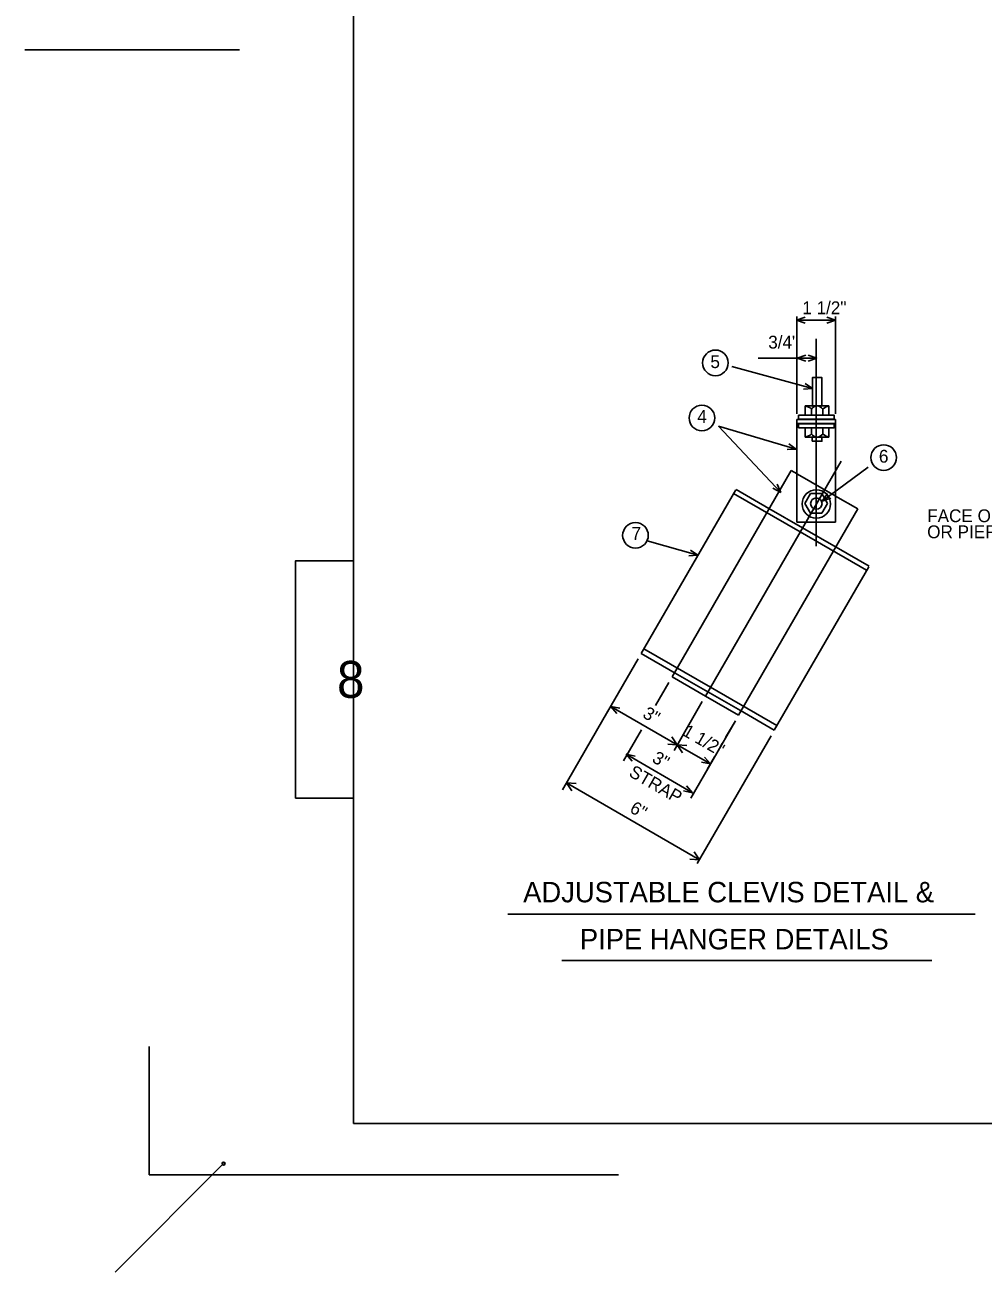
# Model space of a CAD drawing. Extents: x 15000 to 15012.1, y 999.8 to 1007.9.
# Drawn here: x 14999.988 to 15003.107, y 999.805 to 1003.866 of the extents above; entities that cross this region are included whole.
import ezdxf

# ---------------------------------------------------------------- set-up
doc = ezdxf.new("R2010")
doc.units = 0
for name, color, linetype in [('Level 1', 7, 'Continuous'), ('Level 2', 7, 'Continuous'), ('Level 37', 7, 'Continuous'), ('Level 49', 7, 'Continuous')]:
    doc.layers.add(name, color=color, linetype=linetype)

msp = doc.modelspace()

# ---------------------------------------------------------------- linework, layer by layer
at = {"layer": 'Level 1'}
for p, q in [((15001.0578, 1000.2885), (15001.0578, 1007.2814)), ((15000.3918, 1000.5391), (15000.3918, 1000.122)), ((15001.0578, 1000.2885), (15011.5058, 1000.2885)), ((15000.3918, 1000.122), (15001.9196, 1000.122))]:
    msp.add_line(p, q, dxfattribs=at)
msp.add_lwpolyline([(15001.0578, 1002.1216), (15000.8688, 1002.1216), (15000.8688, 1001.3486), (15001.0578, 1001.3486)], close=True, dxfattribs=at)
at = {"layer": 'Level 2'}
for p, q in [((15002.4992, 1002.9043), (15002.5273, 1002.914)), ((15002.4992, 1002.9043), (15002.6266, 1002.9043)), ((15002.5273, 1002.8945), (15002.4992, 1002.9043)), ((15002.5011, 1002.5994), (15002.5011, 1002.9172)), ((15002.5984, 1002.914), (15002.6266, 1002.9043)), ((15002.6266, 1002.9043), (15002.5984, 1002.8945)), ((15002.6261, 1002.5994), (15002.6261, 1002.9172)), ((15002.5636, 1002.8442), (15002.5636, 1002.1688)), ((15002.3744, 1002.7807), (15002.5654, 1002.7807)), ((15002.5015, 1002.7807), (15002.5297, 1002.7904)), ((15002.5297, 1002.7709), (15002.5015, 1002.7807)), ((15002.5373, 1002.7904), (15002.5654, 1002.7807)), ((15002.5654, 1002.7807), (15002.5373, 1002.7709)), ((15002.552, 1002.6819), (15002.289, 1002.7537)), ((15002.5274, 1002.6988), (15002.552, 1002.6819)), ((15002.552, 1002.6819), (15002.5223, 1002.6799)), ((15002.5482, 1002.5953), (15002.5482, 1002.6158)), ((15002.5848, 1002.5953), (15002.5848, 1002.6155)), ((15002.6261, 1002.5808), (15002.5011, 1002.5808)), ((15002.5011, 1002.2474), (15002.5011, 1002.5808)), ((15002.6261, 1002.5683), (15002.5011, 1002.5683)), ((15002.6261, 1002.2474), (15002.6261, 1002.5808)), ((15002.4487, 1002.3439), (15002.2453, 1002.5598)), ((15002.2453, 1002.5598), (15002.4988, 1002.4848)), ((15002.5482, 1002.5542), (15002.5482, 1002.5338)), ((15002.5848, 1002.5543), (15002.5848, 1002.534)), ((15002.4988, 1002.4848), (15002.469, 1002.4834)), ((15002.4745, 1002.5021), (15002.4988, 1002.4848)), ((15002.2028, 1001.6808), (15002.6446, 1002.446)), ((15002.0946, 1001.7433), (15002.4823, 1002.415)), ((15002.5013, 1002.4041), (15002.4823, 1002.415)), ((15002.5833, 1002.3158), (15002.7327, 1002.4263)), ((15002.4364, 1002.3711), (15002.4487, 1002.3439)), ((15002.6251, 1002.3326), (15002.5027, 1002.4033)), ((15001.9943, 1001.8195), (15002.3015, 1002.3518)), ((15002.5113, 1002.2152), (15002.2948, 1002.3402)), ((15002.4097, 1002.2918), (15002.3026, 1002.3537)), ((15002.4487, 1002.3439), (15002.4223, 1002.3578)), ((15002.5268, 1002.308), (15002.5454, 1002.34)), ((15002.5454, 1002.34), (15002.5823, 1002.34)), ((15002.5823, 1002.34), (15002.6008, 1002.308)), ((15002.5833, 1002.3158), (15002.6001, 1002.3403)), ((15002.6117, 1002.3247), (15002.5833, 1002.3158)), ((15002.6269, 1002.3315), (15002.6988, 1002.29)), ((15002.3111, 1001.6183), (15002.6988, 1002.29)), ((15002.5191, 1002.2287), (15002.4097, 1002.2918)), ((15002.5453, 1002.276), (15002.5268, 1002.308)), ((15002.5658, 1002.3081), (15002.5638, 1002.3081)), ((15002.6008, 1002.308), (15002.5823, 1002.276)), ((15002.6261, 1002.2474), (15002.5011, 1002.2474)), ((15002.5823, 1002.276), (15002.5453, 1002.276)), ((15002.5113, 1002.2152), (15002.7278, 1002.0902)), ((15002.5191, 1002.2287), (15002.6285, 1002.1655)), ((15002.1788, 1002.1391), (15002.013, 1002.1861)), ((15002.6285, 1002.1655), (15002.7356, 1002.1037)), ((15002.1788, 1002.1391), (15002.1491, 1002.1375)), ((15002.1543, 1002.1561), (15002.1788, 1002.1391)), ((15002.4272, 1001.5695), (15002.7345, 1002.1018)), ((15001.9838, 1001.8015), (15001.8843, 1001.629)), ((15002.1045, 1001.7558), (15001.9943, 1001.8195)), ((15002.2193, 1001.7094), (15002.0028, 1001.8344)), ((15002.2107, 1001.6945), (15002.1045, 1001.7558)), ((15002.0841, 1001.7253), (15002.0405, 1001.6497)), ((15002.2028, 1001.6808), (15002.0946, 1001.7433)), ((15002.2028, 1001.6808), (15002.3111, 1001.6183)), ((15002.2107, 1001.6945), (15002.317, 1001.6332)), ((15002.2193, 1001.7094), (15002.4358, 1001.5844)), ((15002.1112, 1001.5221), (15001.8947, 1001.6471)), ((15001.8947, 1001.6471), (15001.9239, 1001.6414)), ((15001.9142, 1001.6245), (15001.8947, 1001.6471)), ((15002.1923, 1001.6628), (15002.1008, 1001.504)), ((15002.317, 1001.6332), (15002.4272, 1001.5695)), ((15001.8855, 1001.6312), (15001.7378, 1001.3755)), ((15002.3007, 1001.6003), (15002.1552, 1001.3483)), ((15002.3007, 1001.6003), (15002.2689, 1001.5453)), ((15001.9947, 1001.5703), (15001.9368, 1001.4702)), ((15002.4168, 1001.5515), (15002.1763, 1001.135)), ((15002.2194, 1001.4596), (15002.1112, 1001.5221)), ((15002.1612, 1001.3661), (15001.9447, 1001.4911)), ((15001.9447, 1001.4911), (15001.9739, 1001.4854)), ((15001.9642, 1001.4685), (15001.9447, 1001.4911)), ((15002.1999, 1001.4821), (15002.2194, 1001.4596)), ((15002.2331, 1001.4833), (15002.209, 1001.4415)), ((15002.2194, 1001.4596), (15002.1902, 1001.4652)), ((15001.7507, 1001.3978), (15002.1838, 1001.1478)), ((15002.1417, 1001.3886), (15002.1612, 1001.3661)), ((15002.1612, 1001.3661), (15002.1319, 1001.3717)), ((15001.5599, 1000.97), (15003.0808, 1000.97)), ((15001.7352, 1000.8198), (15002.94, 1000.8198)), ((15000.2811, 999.8052), (15000.6344, 1000.1584))]:
    msp.add_line(p, q, dxfattribs=at)
for points in [[(15002.5823, 1002.6261), (15002.5515, 1002.6261), (15002.5515, 1002.7177), (15002.5823, 1002.7177)], [(15002.528, 1002.6258), (15002.6043, 1002.6258), (15002.6043, 1002.5953), (15002.528, 1002.5953)], [(15002.506, 1002.5951), (15002.6225, 1002.5951), (15002.6225, 1002.5823), (15002.506, 1002.5823)], [(15002.506, 1002.5544), (15002.6225, 1002.5544), (15002.6225, 1002.5672), (15002.506, 1002.5672)], [(15002.528, 1002.5238), (15002.6043, 1002.5238), (15002.6043, 1002.5542), (15002.528, 1002.5542)], [(15002.5508, 1002.5107), (15002.5823, 1002.5107), (15002.5823, 1002.5234), (15002.5508, 1002.5234)]]:
    msp.add_lwpolyline(points, close=True, dxfattribs=at)
for points in [[(15002.0802, 1001.5239), (15002.1112, 1001.5221), (15002.0941, 1001.548)], [(15002.1283, 1001.4962), (15002.1112, 1001.5221), (15002.1422, 1001.5203)], [(15001.7678, 1001.3718), (15001.7507, 1001.3978), (15001.7817, 1001.3959)], [(15002.1527, 1001.1495), (15002.1838, 1001.1478), (15002.1666, 1001.1737)]]:
    msp.add_lwpolyline(points, dxfattribs=at)
for centre, radius in [((15002.2356, 1002.7657), 0.0417), ((15002.1917, 1002.5863), 0.0417), ((15002.7833, 1002.4573), 0.0417), ((15002.5641, 1002.3062), 0.0461), ((15002.5641, 1002.3073), 0.0185), ((15001.9753, 1002.2041), 0.0417)]:
    msp.add_circle(centre, radius, dxfattribs=at)
for centre, radius, start, end in [((15002.5218, 1002.588), 0.0379, 46.108, 80.2684), ((15002.5665, 1002.6034), 0.022, 33.2058, 146.7927), ((15002.6263, 1002.5589), 0.0702, 108.2469, 126.2166), ((15002.5218, 1002.5615), 0.0379, 279.7316, 313.892), ((15002.5665, 1002.5461), 0.022, 213.2073, 326.7942), ((15002.6263, 1002.5906), 0.0702, 233.7834, 251.7531)]:
    msp.add_arc(centre, radius, start, end, dxfattribs=at)
at = {"layer": 'Level 37'}
msp.add_line((15000.6867, 1003.7849), (14999.9877, 1003.7849), dxfattribs=at)
at = {"layer": 'Level 49'}
msp.add_circle((15000.6343, 1000.1584), 0.00506, dxfattribs=at)

# ---------------------------------------------------------------- texts
at = {"layer": 'Level 1'}
msp.add_text('8', height=0.1202, dxfattribs=at).set_placement((15001.0036, 1001.6749))
at = {"layer": 'Level 2'}
for s, height, p in [('1 1/2"', 0.04167, (15002.5183, 1002.9243)), ('3/4"', 0.04167, (15002.4075, 1002.8124)), ('5', 0.0417, (15002.2192, 1002.7487)), ('4', 0.0417, (15002.1765, 1002.5704)), ('6', 0.0417, (15002.7678, 1002.4408)), ('FACE OF COL.', 0.041667, (15002.925, 1002.247)), ('7', 0.0417, (15001.9625, 1002.1894)), ('OR PIER CAP.', 0.041667, (15002.925, 1002.1948)), ('ADJUSTABLE CLEVIS DETAIL &', 0.066667, (15001.6096, 1001.0091)), ('PIPE HANGER DETAILS', 0.066667, (15001.7943, 1000.8558))]:
    msp.add_text(s, height=height, dxfattribs=at).set_placement(p)
for s, p in [(' 3" ', (15001.9821, 1001.6207)), (' 1 1/2" ', (15002.1114, 1001.5629)), (' 3" ', (15002.0128, 1001.4758)), ('STRAP', (15001.9505, 1001.422)), (' 6" ', (15001.9401, 1001.3124))]:
    msp.add_text(s, height=0.04167, rotation=330, dxfattribs=at).set_placement(p)

doc.saveas('drawing.dxf')
